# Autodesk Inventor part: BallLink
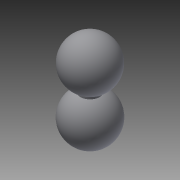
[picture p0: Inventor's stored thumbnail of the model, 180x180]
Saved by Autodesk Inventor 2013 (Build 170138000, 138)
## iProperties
Created: 2013-03
Part Number: BallLink
Material: Generic
Document SubType Name: Modeling
Designer: frankenteddy
Density: 1 g/cm^3
Author: frankenteddy
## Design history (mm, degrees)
sketch "Sketch1"
  geometry: L1 (0, -4.973)-(-2, -4.973); L2 (-2, -4.973)-(-2, -4.473); L3 (0, 4.996)-(0, -4.904); L4 (0, -4.473)-(0, -4.973); L5 (-2, -4.473)-(0, -4.473); L6 (0, -4.55)-(0, -14.45); A1 r 4.95 centre (0.02, 0.046) between (0, 4.996) and (0, -4.904); A2 r 4.95 centre (0.003, -9.5) between (0, -4.55) and (0, -14.45); 1 further point
  constraints: 12 end point, 6 point on circle, 3 perpendicular, 3 point on line, 2 centre point, 1 horizontal, 1 parallel
  dimensions: "d0" = 9.9 diameter of A1; "d3" = 0.5 distance of L1.end L2.end; "d4" = 2 distance of L2.end L5.end; "d5" = 9.9 diameter of A2
revolve "Revolution1" sketch "Sketch1" stored, may be unused: angle "d6" = 90 deg
body "Solid1"
